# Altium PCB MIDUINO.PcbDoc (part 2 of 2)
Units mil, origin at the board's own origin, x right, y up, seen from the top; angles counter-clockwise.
Board outline 26720 x 2625 mil, 2 copper layers (Top Layer, Bottom Layer); 230 components, 129 nets, 640 pads, 170 vias.
Unrouted connection lines stored in the file: 1.
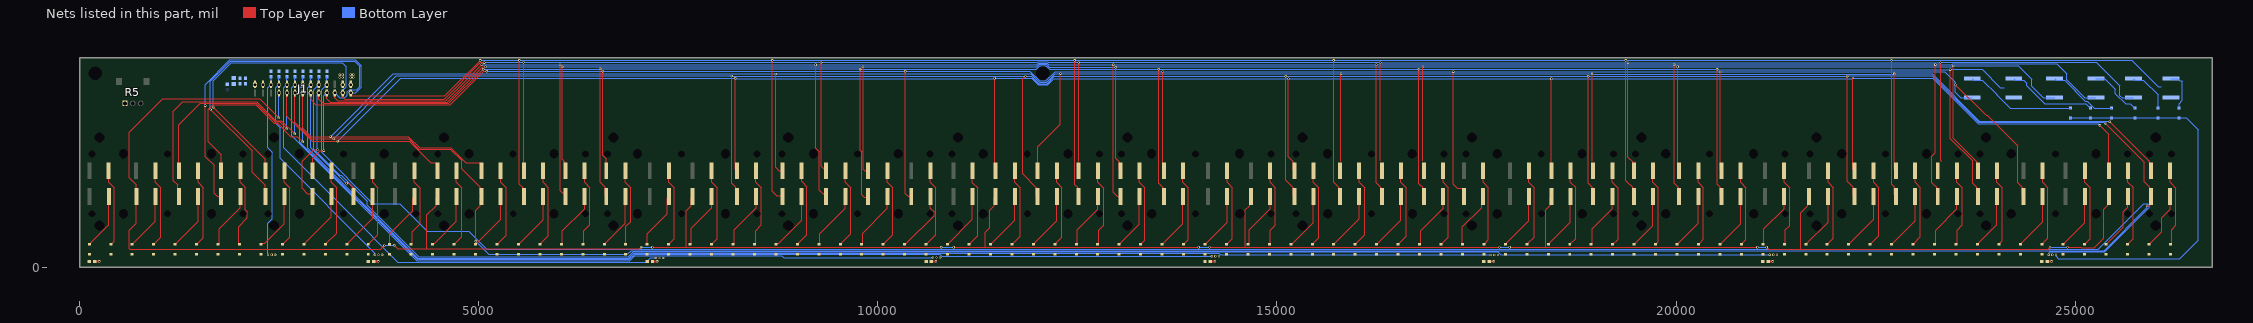
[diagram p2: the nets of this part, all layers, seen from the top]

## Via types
v1: diameter 30, hole 15, Top Layer to Bottom Layer, 145 vias
v2: diameter 54.72, hole 35.04, Top Layer to Bottom Layer, 25 vias

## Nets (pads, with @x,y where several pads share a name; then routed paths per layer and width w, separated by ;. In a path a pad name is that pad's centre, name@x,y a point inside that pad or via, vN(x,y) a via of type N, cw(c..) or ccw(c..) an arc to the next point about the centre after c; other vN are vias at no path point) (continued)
COL4: H4_ROW1.1 H4_ROW2.1 H4_ROW3.1 H4_ROW4.1 H4_ROW5.1 H4_ROW6.1 H4_ROW7.1 H4_ROW8.1 J1.8 | length 33504.2
  Top Layer w10: v1(2494.12,1869.12) 2494.12,1874.42 2258.54,2110 1042.63,2110 620,1687.37 620,1120.44 710,1030.44 H4_ROW1.1@710,885 710,546.93 625.14,462.07 625.14,229.86 631,224 3772.44,224 v1(3819,270.56) ; v1(3942.78,272.78) 3985.56,230 4350,230 ; H4_ROW2.1@4481,885 4466,870 4466,771 4350,655 4350,230 ; v1(7035,251) 7034.57,251 7013.57,230 4350,230 ; v1(7176.4,250.12) 7176.52,250 7600,250 ; H4_ROW3.1@7679,885 7665.86,871.86 7665.86,770.86 7600,705 7600,250 ; v1(10795,250.12) 10794.88,250 7600,250 ; v1(10950,250.12) 10950.12,250 11345,250 ; H4_ROW4.1@11476,886 11461.86,871.86 11461.86,771.86 11400.5,710.5 11400.5,490.5 11345,435 11345,250 ; v1(14019,250.12) 14018.88,250 11345,250 ; v1(14155,250.12) 14155.12,250 14606.35,250 ; H4_ROW5.1@14675,885 14660.86,870.86 14660.86,770.86 14606.35,716.35 14606.35,250 ; v1(17789,250.12) 17788.88,250 14606.35,250 ; v1(17915,250.12) 17915.12,250 18369.47,250 ; H4_ROW6.1@18438,885 18423,870 18423,773 18370.28,720.28 18370.28,250.81 18369.47,250 ; v1(21019,250.12) 21018.88,250 18369.47,250 ; v1(21135,250.12) 21135,250 21160,225 21556.25,225 ; H4_ROW7.1@21665,885 21650.86,870.86 21650.86,770.86 21561.25,681.25 21561.25,230 21556.25,225 ; v1(24685,250.12) 24685,247.43 24662.57,225 21561.25,225 21556.25,225 ; v1(24905,250.12) 25072.65,250.12 25077.76,245 25240,245 25358.92,363.92 25358.92,723.92 25407,772 25407,871 H4_ROW8.1@25422,886
  Bottom Layer w10: v1(2494.12,1869.12) 2496.06,1871.06 2496.06,2183.06 v2(2498,2185) ; v1(3819,270.56) 3820.11,271.67 3941.67,271.67 v1(3942.78,272.78) ; v1(7035,251) 7035.44,250.56 7175.96,250.56 v1(7176.4,250.12) ; v1(10795,250.12) v1(10950,250.12) ; v1(14019,250.12) v1(14155,250.12) ; v1(17789,250.12) v1(17915,250.12) ; v1(21019,250.12) v1(21135,250.12) ; v1(24685,250.12) v1(24905,250.12)
COL5: H5_ROW1.1 H5_ROW2.1 H5_ROW3.1 H5_ROW4.1 H5_ROW5.1 H5_ROW6.1 H5_ROW7.1 H5_ROW8.1 J1.10 | length 34308.3
  Top Layer w10: H5_ROW1.1@1244,1207 1244,1784 1514,2054 2213.37,2054 2448.69,1818.69 2507.77,1818.69 v1(2595.19,1731.27) ; v2(2598,2185) J1.10@2598,2180.08 2598,1892.51 2912.51,1578 4129.79,1578 4400.79,1307 4461,1307 4481,1287 H5_ROW2.1@4481,1207 ; v1(8214.64,2366) 8214.64,1226.36 H5_ROW3.1@8234,1207 ; v1(11462.97,2366) 11462.97,1221.03 H5_ROW4.1@11476,1208 ; v1(15145,2361) 15145,1380 15203.86,1321.14 15203.86,1221.14 H5_ROW5.1@15218,1207 ; H5_ROW6.1@18438,1207 18439.07,1208.07 v1(18439.07,2361) ; v1(22217,2369) 22216,2368 22216,1227 H5_ROW7.1@22236,1207 ; v1(25310,1775) 25422,1663 H5_ROW8.1@25422,1208
  Bottom Layer w10: v1(2595.19,1731.27) 2596.6,1732.67 2596.6,2183.6 v2(2598,2185) ; v1(3232.01,1578.48) 4022.54,2369 8157.04,2369 8158.04,2368 8179.58,2368 8180.58,2369 8211.64,2369 v1(8214.64,2366) ; v1@8214.64,2365.56 8217.2,2363 11459.96,2363 v1(11462.97,2366) ; v1@11463.97,2364 11927.35,2364 12007.35,2284 12126.75,2284 12203.58,2360.83 15144.83,2360.83 v1(15145,2361) ; v1@15145.08,2360.91 15145.17,2361 v1(18439.07,2361) ; v1@18439.07,2360.83 22203.42,2360.83 22211.59,2369 v1(22217,2369) ; v1@22220,2369 23216.25,2369 23788.25,1797 25288,1797 v1(25310,1775)
COL6: H6_ROW1.1 H6_ROW2.1 H6_ROW3.1 H6_ROW4.1 H6_ROW5.1 H6_ROW6.1 H6_ROW7.1 H6_ROW8.1 J1.12 | length 60224.7
  Top Layer w10: H6_ROW1.1@1245,885 1230.86,899.14 1230.86,1029.14 1175,1085 1175,1955 1290,2070 2220,2070 2455,1835 2528.23,1835 v1(2694.12,1669.12) ; v2(2698,2185) J1.12@2698,2180.08 2698,1815.14 2904.14,1609 v1(3184.23,1609) 4121.42,1609 4251.42,1479 4646,1479 4785,1340 4785,1235 5021,999 5021,900 H6_ROW2.1@5036,885 5021,870 5021,771 4963.22,713.22 v1(4963.22,324.72) ; v1(8168.81,2394) 8168.81,1445.53 8168.81,1051.19 8219,1001 8219,900 H6_ROW3.1@8234,885 ; v1(11850,2390) 11817.7,2357.7 11817.7,1167.3 11988,997 11988,900 H6_ROW4.1@12003,885 ; v1(15110,2390) 15110,1090 15203,997 15203,900 H6_ROW5.1@15218,885 ; v1(18901.66,2392.07) 18900.41,2390.82 18900.41,1049.59 18949.86,1000.14 18949.86,898.14 H6_ROW6.1@18962,886 ; v1(22146.03,2393) 22145,2391.97 22145,1075 22221,999 22221,900 H6_ROW7.1@22236,885 ; v1(25385,1795) 25865,1315 25865,1070 25935.86,999.14 25935.86,898.14 H6_ROW8.1@25949,885 ; v1(25900,770) 25940,770
  Bottom Layer w10: v1(2694.12,1669.12) 2696.06,1671.06 2696.06,2183.06 v2(2698,2185) ; v1(3184.23,1609) 3184.23,1614.23 3189.46,1614.23 3970.23,2395 8167.81,2395 8170.81,2392 11848,2392 v1(11850,2390) 11923.98,2390 12013.98,2300 12120.12,2300 12212.19,2392.07 15107.93,2392.07 v1(15110,2390) 15111.04,2391.04 18900.63,2391.04 18902.13,2392.54 22145.57,2392.54 v1(22146.03,2393) ; v1(4963.22,324.72) 4963.22,321.78 5125,160 6860,160 6908.12,208.12 25363.12,208.12 25900,745 v1(25900,770) ; v1@22148.72,2393.06 22150.66,2395 23212.88,2395 23794.88,1813 25361.59,1813 25379.59,1795 v1(25385,1795)
COL7: H7_ROW1.1 H7_ROW2.1 H7_ROW3.1 H7_ROW4.1 H7_ROW5.1 H7_ROW6.1 H7_ROW7.1 H7_ROW8.1 J1.14 | length 35615.5
  Top Layer w10: H7_ROW1.1@1774,1208 1774,1406 1610,1570 1610,1980 1666,2036 1839,2036 1840,2035 2205,2035 2440,1800 2480,1800 2645,1635 2728.23,1635 v1(2794.12,1569.12) ; v2(2798,2185) J1.14@2798,2180.08 2798,1737.76 2900.76,1635 v1(3145,1635) 4120,1635 4260,1495 4652.63,1495 4840.63,1307 5016,1307 5036,1287 H7_ROW2.1@5036,1207 ; v1(8720,2420) 8720,1250 8762,1208 H7_ROW3.1@8806,1208 ; H7_ROW4.1@12003,1207 12003,1505.85 12288.57,1791.43 v1(12288.57,2424) ; 15802.81,1327.81 v1(15802.81,2424) ; v1(18947,2421) 18950,2418 18950,1325 ; v1(22735.58,2421) 22736,2420.58 22736,1227 H7_ROW7.1@22756,1207 ; v1(25434,1821) 25929,1326 25929,1312 25949,1292 H7_ROW8.1@25949,1207
  Bottom Layer w10: v1(2794.12,1569.12) 2796.06,1571.06 2796.06,2183.06 v2(2798,2185) ; v1(3145,1635) 3931,2421 8719,2421 v1(8720,2420) 11916.61,2420 12020.61,2316 12113.49,2316 12221.49,2424 v1(15802.81,2424) 15805.81,2421 v1(18947,2421) ; v1@18947,2419 22733.58,2419 v1(22735.58,2421) ; v1@22736.16,2420.43 22737.31,2421.58 23208.93,2421.58 23800.51,1830 25419.59,1830 25428.59,1821 v1(25434,1821)
COL8: H13_ROW1.1 H13_ROW2.1 H13_ROW3.1 H13_ROW4.1 H13_ROW5.1 H13_ROW6.1 H13_ROW7.1 H13_ROW8.1 J1.16 | length 31775.4
  Top Layer w10: J1.16@2898,2180.08 v2(2898,2185) 2900,2183 2900,2095 2961,2034 4644,2034 5062.73,2452.73 v1(5100,2452.73) ; v1(3345,1050) 3370,1050 3420.86,999.14 3420.86,896.14 H13_ROW1.1@3432,885 ; v1(6553.74,2455.48) 6553.74,1401.47 6598,1357.21 H13_ROW2.1@6598,1207 ; v1(10345,2455) 10345,920 10380,885 H13_ROW3.1@10419,885 ; v1(13570,2451) 13570,1220 H13_ROW4.1@13583,1207 ; v1(17208,2450) 17208,1037 17260,985 17325,985 17345,965 H13_ROW5.1@17345,885 ; v1(20555,2445) 20555,1223 H13_ROW6.1@20570,1208 ; v1(23501,2284.57) 23885.2,1900.37 23899.63,1900.37 24280,1520 24280,1060 24339,1001 24339,900 H13_ROW7.1@24354,885
  Bottom Layer w10: v2(2898,2185) 2898,1492.6 3340.6,1050 v1(3345,1050) ; v1(5100,2452.73) 5101.38,2454.11 6552.37,2454.11 v1@6558.37,2460.11 ; v1(6553.74,2455.48) v1@6558.37,2460.11 ; v1@20552.53,2447.53 20555,2450 23367.63,2450 23501,2316.63 v1(23501,2284.57) ; v1(20555,2445) 20552.5,2447.5 17210.5,2447.5 17207.5,2450.5 13570.5,2450.5 v1(13570,2451) 13569,2450 12224.86,2450 12106.86,2332 12027.24,2332 11906.5,2452.73 10345,2452.73 10342.51,2455.23 6562.98,2455.23 6558.37,2459.84 v1@6558.37,2460.11 ; v1@23500,2281.92 23500,2190 23567.99,2122.01 H13_ROW8.1@23712,2122.01
COL9: H12_ROW1.1 H12_ROW2.1 H12_ROW3.1 H12_ROW4.1 H12_ROW5.1 H12_ROW6.1 H12_ROW7.1 H12_ROW8.1 J1.18 | length 32916.9
  Top Layer w10: H12_ROW1.1@2915,885 2915,900 2895,920 2855,920 2790,985 2790,1325 2935,1470 v1(2980,1470) ; v2(2998,2185) 2998,2102 3050,2050 4625,2050 5054.48,2479.49 v1(5056.25,2479.49) ; v1(6521.22,2484) 6521.22,1063.78 6583,1002 6583,900 H12_ROW2.1@6598,885 ; v1(9778.74,2481.23) 9778.74,1467.04 9800.3,1445.48 9800.3,904.7 9830,875 9870,875 H12_ROW3.1@9880,885 ; v1(13519,2479) 13520,2478 13520,1050 13570.86,999.14 13570.86,897.14 H12_ROW4.1@13583,885 ; v1(16779.25,2479.25) 16780,2478.5 16780,1045 16827,998 16827,900 H12_ROW5.1@16842,885 ; v1(20515,2476.53) 20515,1040 20555,1000 20555,901 H12_ROW6.1@20570,886 ; v1(23435,2475) 23435,1610 23715,1330 23715,1050 23766,999 23766,900 H12_ROW7.1@23781,885
  Bottom Layer w10: v1(2980,1470) 2980,2154.9 2998,2172.9 v2(2998,2185) ; v1(5056.25,2479.49) 5058.51,2481.74 6518.96,2481.74 v1(6521.22,2484) ; v1@6523.22,2482.61 9777.36,2482.61 v1(9778.74,2481.23) 11983.85,2481.23 12026.63,2524 12106.76,2524 12154.69,2476.07 13516.07,2476.07 13519.5,2479.5 13519.88,2479.12 16779.12,2479.12 v1(16779.25,2479.25) 16782.43,2476.07 v1@20514.93,2476.07 ; v1(20515,2476.53) 20515.76,2475.76 23434.69,2475.76 23435,2476.07 23838.93,2476.07 24065,2250 24110,2250
COL10: H11_ROW1.1 H11_ROW2.1 H11_ROW3.1 H11_ROW4.1 H11_ROW5.1 H11_ROW6.1 H11_ROW7.1 H11_ROW8.1 J1.20 | length 31087.7
  Top Layer w10: H11_ROW1.1@2915,1207 2920,1212 2920,1365 3015,1460 v1(3060,1460) ; v2(3098,2185) J1.20@3098,2180.08 3098,2107 3139,2066 4606,2066 5050,2510 v1(5085,2510) ; v1(6045,2510) 6045,1349 6072.86,1321.14 6072.86,1307 6074.73,1305.13 H11_ROW2.1@6088.87,1305.13 ; v1(9815,2510) 9816.3,2508.7 9816.3,1228.7 9835,1210 9878,1210 H11_ROW3.1@9880,1208 ; v1(12980,2505) 12980,1365 13023,1322 13023,1223 H11_ROW4.1@13038,1208 ; 16830,1330 v1(16830,2510) ; v1(20020,2510.12) 20020,1227 H11_ROW6.1@20040,1207 ; v1(23475,2520) 23475,1615 23768.86,1321.14 23768.86,1219.14 H11_ROW7.1@23781,1207
  Bottom Layer w10: v1(3060,1460) 3060,2147 v2(3098,2185) ; v1(5085,2510) v1(6045,2510) v1(9815,2510) 11990,2510 12020,2540 12113.39,2540 12148.39,2505 12974.88,2505 12980,2510.12 v1(20020,2510.12) ; v1@20022.42,2510.12 23459.7,2510.12 23469.59,2520 24290,2520 24455,2355 24455,2267.19 24600.18,2122.01 H11_ROW8.1@24742,2122.01
COL11: H10_ROW1.1 H10_ROW2.1 H10_ROW3.1 H10_ROW4.1 H10_ROW5.1 H10_ROW6.1 H10_ROW7.1 H10_ROW8.1 J1.22 | length 37148.9
  Top Layer w10: v1(1640.88,1974.12) 2160,1455 2160,1190 2327,1023 H10_ROW1.1@2327,885 ; v2(3198,2185) 3198,2122 3235,2085 4585,2085 5038,2538 v1(5039,2538) ; v1(6018.88,2536.12) 6018.88,956.12 6044.74,930.26 6067,930.26 6087,910.26 H10_ROW2.1@6087,885 ; v1(9221.12,2536.12) 9221.12,1490.47 9265,1446.58 9265,965 9319.86,910.14 9334,910.14 9354,890.14 H10_ROW3.1@9354,885 ; v1(12948.88,2536.12) 12948.88,936.12 12999,886 H10_ROW4.1@13038,886 ; v1(16245,2538) 16245,1055 16299.86,1000.14 16299.86,900.14 H10_ROW5.1@16314,886 ; v1(19976.12,2536.12) 19976.12,1048.88 20025.86,999.14 20025.86,899.14 H10_ROW6.1@20040,885 ; v1(23250,2537) 23250,1434.42 23205,1389.42 23205,1060 23265.86,999.14 23265.86,898.14 H10_ROW7.1@23279,885
  Bottom Layer w10: v1(1640.88,1974.12) 1640,1975 1640,2330 1889,2579 3445.14,2579 3510,2514.14 3510,2260 3473.36,2223.36 3382.11,2223.36 3355,2196.25 3355,2155 3324.96,2124.96 3258.04,2124.96 v2(3198,2185) ; v1(5039,2538) 5040.88,2536.12 v1(6018.88,2536.12) v1(9221.12,2536.12) 11991.12,2536.12 12011,2556 12120.02,2556 12139.9,2536.12 v1(12948.88,2536.12) 12949.83,2537.06 16244.06,2537.06 v1(16245,2538) ; v1@16245,2540 16248.88,2536.12 v1(19976.12,2536.12) 19976.56,2536.56 23249.56,2536.56 v1(23250,2537) ; v1@23251.5,2538.5 23253.88,2536.12 23454.35,2536.12 23464.23,2546 24769,2546 24895,2420 24895,2345 25117.99,2122.01 H10_ROW8.1@25261,2122.01
COL12: H9_ROW1.1 H9_ROW2.1 H9_ROW3.1 H9_ROW4.1 H9_ROW5.1 H9_ROW6.1 H9_ROW7.1 H9_ROW8.1 J1.24 | length 34255
  Top Layer w10: v1(1675,2005) 2327,1353 H9_ROW1.1@2327,1207 ; v2(3298,2185) 3299.14,2183.86 3299.14,2125.86 3320,2105 4568.23,2105 5027.23,2564 5068.68,2564 v1(5070.57,2562.12) ; v1(5561.34,2566) 5561.34,1292.66 H9_ROW2.1@5565,1289 ; v1(9290,2564) 9290,1265 9319.86,1235.14 9334,1235.14 9354,1215.14 H9_ROW3.1@9354,1208 ; 12515,1325 12515,2563.81 v1(12515.19,2564) ; v1(16294.5,2564) 16295,2563.5 16295,1330 ; v1(19398,2562.12) 19398,1377 19456,1319 19456,1222 H9_ROW6.1@19471,1207 ; 19480,1320 19482.86,1317.14 19491.14,1317.14 ; v1(23313.41,2564) 23314,2563.41 23314,1331 23320,1325
  Bottom Layer w10: v1(1675,2005) 1675,2335 1900,2560 3288,2560 3340,2508 3340,2260 3301.45,2221.45 3301.45,2188.45 v2(3298,2185) ; v1(5070.57,2562.12) 5072.45,2564 5559.34,2564 v1(5561.34,2566) 5563.34,2564 v1(9290,2564) 10710.15,2564 11994,2564 12002,2572 12126.65,2572 12134.65,2564 v1(12515.19,2564) ; v1@12515.51,2564.33 12515.84,2564 v1(16294.5,2564) 16295.5,2563 19397.12,2563 v1(19398,2562.12) ; v1@19398.06,2562.06 19399,2563 23312.41,2563 v1(23313.41,2564) 25266,2564 25560,2270 25560,2150 25587.99,2122.01 H9_ROW8.1@25731,2122.01
COL13: H8_ROW1.1 H8_ROW2.1 H8_ROW3.1 H8_ROW4.1 H8_ROW5.1 H8_ROW6.1 H8_ROW7.1 H8_ROW8.1 J1.26 | length 37547
  Top Layer w10: v1(1575,2023) 1575,1385 1685,1275 1685,925 1724,886 H8_ROW1.1@1774,886 ; v2(3398,2185) 3398,2154.96 3407.96,2145 4577.49,2145 5020,2587.51 v1(5020,2590) ; v1(5510,2590) 5510,1040 5552,998 5552,900 H8_ROW2.1@5567,885 ; v1(8680,2590) 8680,950 8735,895 8796,895 H8_ROW3.1@8806,885 ; v1(12465,2590) 12465,1035 12502,998 12502,901 H8_ROW4.1@12517,886 ; v1(15710,2590) 15710,1065 15776,999 15776,901 H8_ROW5.1@15791,886 ; v1(19371.01,2590) 19371.01,1083.99 19456,999 19456,900 H8_ROW6.1@19471,885 ; v1(22700,2590) 22700,1040 22736,1004 22736,905 H8_ROW7.1@22756,885
  Bottom Layer w10: v1(1575,2023) 1575,2287.63 1882.37,2595 3451.77,2595 3526,2520.77 3526,2251 3460,2185 v2(3398,2185) ; v1(5020,2590) v1(5510,2590) 5512,2592 8678,2592 v1(8680,2590) v1(12465,2590) v1(15710,2590) v1(19371.01,2590) v1(22700,2590) 25710,2590 26040,2260 26080,2260
GND: C1.1 C2.2 C3.1 C4_ROW1.1 C4_ROW2.1 C4_ROW3.1 C4_ROW4.1 C4_ROW5.1 C4_ROW6.1 C4_ROW7.1 C4_ROW8.1 J1.23 J1.25 R5.1 R6_ROW1.1 R6_ROW2.1 R6_ROW3.1 R6_ROW4.1 R6_ROW5.1 R6_ROW6.1 R6_ROW7.1 R6_ROW8.1 | length 465.5
  Top Layer w25: R6_ROW1.1@188.46,72 v1@246.65,72 ; R6_ROW2.1@3683.46,72 v1(3741.65,72) ; R6_ROW3.1@7177.1,72 v1(7235.29,72) ; R6_ROW4.1@10671.42,72 v1(10729.61,72) ; R6_ROW5.1@14165.74,72 v1(14223.93,72) ; R6_ROW6.1@17660.06,72 v1(17718.25,72) ; R6_ROW7.1@21154.38,72 v1(21212.57,72) ; R6_ROW8.1@24648.7,72 v1(24706.89,72)
  other v1: 246.65,72 3260,2375 3295,2375 3395,2375 3430,2375 3260,2410 3295,2410 3395,2410 3430,2410
  other v2: 3298,2285 3398,2285
NetD1_ROW1_1: D1_ROW1.1 H1_ROW1.2 | length 966.4
  Top Layer w10: H1_ROW1.2@365,1207 365,1061.55 432,994.55 432,326.23 391.78,286.01 D1_ROW1.1@390.79,286.01
NetD1_ROW2_1: D1_ROW2.1 H1_ROW2.2 | length 999.3
  Top Layer w10: D1_ROW2.1@3616.32,286.01 3617.3,286.01 3630.02,298.72 3630.02,299.71 3738,407.69 3738,994.55 3672,1060.55 H1_ROW2.2@3672,1207
NetD1_ROW3_1: D1_ROW3.1 H1_ROW3.2 | length 979.4
  Top Layer w10: D1_ROW3.1@7379.43,286.01 7380.42,286.01 7393.13,298.72 7393.13,299.71 7451,357.58 7451,992.55 7383,1060.55 H1_ROW3.2@7383,1207
NetD1_ROW4_1: D1_ROW4.1 H1_ROW4.2 | length 1000.3
  Top Layer w10: D1_ROW4.1@10604.96,286.01 10605.94,286.01 10618.66,298.72 10618.66,299.71 10727,408.05 10727,992.55 10659,1060.55 H1_ROW4.2@10659,1207
NetD1_ROW5_1: D1_ROW5.1 H1_ROW5.2 | length 978.3
  Top Layer w10: D1_ROW5.1@14368.07,286.01 14369.06,286.01 14381.77,298.72 14381.77,299.71 14440,357.94 14440,995.55 14375,1060.55 H1_ROW5.2@14375,1207
NetD1_ROW6_1: D1_ROW6.1 H1_ROW6.2 | length 971.9
  Top Layer w10: H1_ROW6.2@17585,1207 17585,1060.55 17650,995.55 17650,342.41 17607.3,299.71 17607.3,298.72 17594.58,286.01 D1_ROW6.1@17593.6,286.01
NetD1_ROW7_1: D1_ROW7.1 H1_ROW7.2 | length 976.6
  Top Layer w10: H1_ROW7.2@21355,1207 21355,1060.55 21422.3,993.25 21422.3,521.05 21370.41,469.16 21370.41,298.72 21357.69,286.01 D1_ROW7.1@21356.71,286.01
NetD1_ROW8_1: D1_ROW8.1 H1_ROW8.2 | length 981.1
  Top Layer w10: D1_ROW8.1@24582.24,286.01 24583.22,286.01 24595.94,298.72 24595.94,299.71 24660,363.77 24660,994.55 24594,1060.55 H1_ROW8.2@24594,1207
NetD2_ROW1_1: D2_ROW1.1 H2_ROW1.2 | length 700.6
  Top Layer w10: D2_ROW1.1@122,286.01 122.98,286.01 366,529.02 H2_ROW1.2@366,885
NetD2_ROW2_1: D2_ROW2.1 H2_ROW2.2 | length 726.9
  Top Layer w10: D2_ROW2.1@3885.11,286.01 3885.11,417.9 4174,706.79 4174,865 H2_ROW2.2@4194,885
NetD2_ROW3_1: D2_ROW3.1 H2_ROW3.2 | length 711.8
  Top Layer w10: D2_ROW3.1@7110.64,286.01 7110.64,415.68 7363,668.04 7363,865 H2_ROW3.2@7383,885
NetD2_ROW4_1: D2_ROW4.1 H2_ROW4.2 | length 727.9
  Top Layer w10: D2_ROW4.1@10873.75,286.01 10874.74,286.01 11186,597.27 H2_ROW4.2@11186,884
NetD2_ROW5_1: D2_ROW5.1 H2_ROW5.2 | length 713.8
  Top Layer w10: D2_ROW5.1@14099.28,286.01 14100.26,286.01 14375,560.75 H2_ROW5.2@14375,885
NetD2_ROW6_1: D2_ROW6.1 H2_ROW6.2 | length 722
  Top Layer w10: D2_ROW6.1@17862.39,286.01 17863.38,286.01 18158,580.63 H2_ROW6.2@18158,885
NetD2_ROW7_1: D2_ROW7.1 H2_ROW7.2 | length 710.2
  Top Layer w10: D2_ROW7.1@21087.92,286.01 21088.9,286.01 21101.62,298.72 21101.62,479.41 21355,732.79 H2_ROW7.2@21355,885
NetD2_ROW8_1: D2_ROW8.1 H2_ROW8.2 | length 712.4
  Top Layer w10: D2_ROW8.1@24851.03,286.01 24852.01,286.01 25121,554.99 H2_ROW8.2@25121,886
NetD3_ROW1_1: D3_ROW1.1 H3_ROW1.2 | length 984.8
  Top Layer w10: D3_ROW1.1@928.38,286.01 929.37,286.01 1015,371.64 1015,995.55 949,1061.55 H3_ROW1.2@949,1207
NetD3_ROW2_1: D3_ROW2.1 H3_ROW2.2 | length 998.9
  Top Layer w10: D3_ROW2.1@4153.91,286.01 4154.89,286.01 4167.61,298.72 4167.61,445.26 4267.3,544.95 4267.3,987.25 4194,1060.55 H3_ROW2.2@4194,1207
NetD3_ROW3_1: D3_ROW3.1 H3_ROW3.2 | length 978.7
  Top Layer w10: D3_ROW3.1@7917.02,286.01 7918,286.01 7930.72,298.72 7930.72,299.71 7987,355.99 7987,992.55 7919,1060.55 H3_ROW3.2@7919,1207
NetD3_ROW4_1: D3_ROW4.1 H3_ROW4.2 | length 992.4
  Top Layer w10: D3_ROW4.1@11142.55,286.01 11143.53,286.01 11156.25,298.72 11156.25,299.71 11251,394.46 11251,994.55 11186,1059.55 H3_ROW4.2@11186,1206
NetD3_ROW5_1: D3_ROW5.1 H3_ROW5.2 | length 981.2
  Top Layer w10: D3_ROW5.1@14905.66,286.01 14906.64,286.01 14919.36,298.72 14919.36,463.64 14982.3,526.58 14982.3,993.25 14915,1060.55 H3_ROW5.2@14915,1207
NetD3_ROW6_1: D3_ROW6.1 H3_ROW6.2 | length 985.7
  Top Layer w10: D3_ROW6.1@18131.18,286.01 18132.17,286.01 18144.89,298.72 18144.89,299.71 18222,376.82 18222,996.55 18158,1060.55 H3_ROW6.2@18158,1207
NetD3_ROW7_1: D3_ROW7.1 H3_ROW7.2 | length 979.8
  Top Layer w10: D3_ROW7.1@21894.3,286.01 21895.28,286.01 21908,298.72 21908,299.71 21970,361.71 21970,995.55 21905,1060.55 H3_ROW7.2@21905,1207
NetD3_ROW8_1: D3_ROW8.1 H3_ROW8.2 | length 977.7
  Top Layer w10: D3_ROW8.1@25119.82,286.01 25120.81,286.01 25133.52,298.72 25133.52,299.71 25187,353.18 25187,995.55 25121,1061.55 H3_ROW8.2@25121,1208
NetD4_ROW1_1: D4_ROW1.1 H4_ROW1.2 | length 719.9
  Top Layer w10: D4_ROW1.1@659.59,286.01 660.57,286.01 950,575.44 H4_ROW1.2@950,885
NetD4_ROW2_1: D4_ROW2.1 H4_ROW2.2 | length 729
  Top Layer w10: D4_ROW2.1@4422.7,286.01 4435.42,298.72 4446.38,298.72 4721,573.35 H4_ROW2.2@4721,885
NetD4_ROW3_1: D4_ROW3.1 H4_ROW3.2 | length 711.7
  Top Layer w10: D4_ROW3.1@7648.23,286.01 7649.21,286.01 7661.93,298.72 7661.93,486.93 7919,744 H4_ROW3.2@7919,885
NetD4_ROW4_1: D4_ROW4.1 H4_ROW4.2 | length 726.8
  Top Layer w10: D4_ROW4.1@11411.34,286.01 11412.32,286.01 11716,589.68 H4_ROW4.2@11716,886
NetD4_ROW5_1: D4_ROW5.1 H4_ROW5.2 | length 714.8
  Top Layer w10: D4_ROW5.1@14636.87,286.01 14637.85,286.01 14650.57,298.72 14650.57,468.36 14915,732.79 H4_ROW5.2@14915,885
NetD4_ROW6_1: D4_ROW6.1 H4_ROW6.2 | length 714.7
  Top Layer w10: D4_ROW6.1@18399.98,286.01 18400.96,286.01 18678,563.05 H4_ROW6.2@18678,885
NetD4_ROW7_1: D4_ROW7.1 H4_ROW7.2 | length 716
  Top Layer w10: D4_ROW7.1@21625.5,286.01 21638.22,298.72 21640.38,298.72 21905,563.35 H4_ROW7.2@21905,885
NetD4_ROW8_1: D4_ROW8.1 H4_ROW8.2 | length 713.8
  Top Layer w10: D4_ROW8.1@25388.62,286.01 25389.6,286.01 25604.7,501.11 25604.7,691.49 25662,748.79 H4_ROW8.2@25662,886
NetD5_ROW1_1: D5_ROW1.1 H5_ROW1.2 | length 984.5
  Top Layer w10: D5_ROW1.1@1465.97,286.01 1466.95,286.01 1551,370.05 1551,994.55 1484,1061.55 H5_ROW1.2@1484,1207
NetD5_ROW2_1: D5_ROW2.1 H5_ROW2.2 | length 988.5
  Top Layer w10: D5_ROW2.1@4691.49,286.01 4692.48,286.01 4705.2,298.72 4705.2,299.71 4787,381.51 4787,994.55 4721,1060.55 H5_ROW2.2@4721,1207
NetD5_ROW3_1: D5_ROW3.1 H5_ROW3.2 | length 987.2
  Top Layer w10: D5_ROW3.1@8454.61,286.01 8455.59,286.01 8468.31,298.72 8468.31,458.11 8542.3,532.1 8542.3,992.25 8474,1060.55 H5_ROW3.2@8474,1208
NetD5_ROW4_1: D5_ROW4.1 H5_ROW4.2 | length 992.9
  Top Layer w10: D5_ROW4.1@11680.13,286.01 11681.12,286.01 11693.83,298.72 11693.83,299.71 11783,388.87 11783,994.55 11716,1061.55 H5_ROW4.2@11716,1208
NetD5_ROW5_1: D5_ROW5.1 H5_ROW5.2 | length 981.5
  Top Layer w10: D5_ROW5.1@15443.25,286.01 15444.23,286.01 15456.95,298.72 15456.95,299.71 15523,365.76 15523,995.55 15458,1060.55 H5_ROW5.2@15458,1207
NetD5_ROW6_1: D5_ROW6.1 H5_ROW6.2 | length 977.6
  Top Layer w10: D5_ROW6.1@18668.77,286.01 18669.76,286.01 18682.47,298.72 18682.47,299.71 18741,358.24 18741,997.55 18678,1060.55 H5_ROW6.2@18678,1207
NetD5_ROW7_1: D5_ROW7.1 H5_ROW7.2 | length 993.7
  Top Layer w10: D5_ROW7.1@22431.89,286.01 22432.87,286.01 22445.59,298.72 22445.59,299.71 22541,395.12 22541,995.55 22476,1060.55 H5_ROW7.2@22476,1207
NetD5_ROW8_1: D5_ROW8.1 H5_ROW8.2 | length 977.5
  Top Layer w10: D5_ROW8.1@25657.41,286.01 25658.4,286.01 25726,353.61 25726,997.55 25662,1061.55 H5_ROW8.2@25662,1208
NetD6_ROW1_1: D6_ROW1.1 H6_ROW1.2 | length 718.8
  Top Layer w10: D6_ROW1.1@1197.18,286.01 1198.16,286.01 1485,572.85 H6_ROW1.2@1485,885
NetD6_ROW2_1: D6_ROW2.1 H6_ROW2.2 | length 730.3
  Top Layer w10: D6_ROW2.1@4960.29,286.01 4961.27,286.01 5276,600.74 H6_ROW2.2@5276,885
NetD6_ROW3_1: D6_ROW3.1 H6_ROW3.2 | length 719.3
  Top Layer w10: D6_ROW3.1@8185.81,286.01 8186.8,286.01 8199.51,298.72 8199.51,469.51 8474.48,744.48 8474.48,884.52 H6_ROW3.2@8474,885
NetD6_ROW4_1: D6_ROW4.1 H6_ROW4.2 | length 721.4
  Top Layer w10: D6_ROW4.1@11948.93,286.01 11949.91,286.01 12243,579.1 H6_ROW4.2@12243,885
NetD6_ROW5_1: D6_ROW5.1 H6_ROW5.2 | length 724.2
  Top Layer w10: D6_ROW5.1@15174.45,286.01 15187.17,298.72 15200.38,298.72 15458,556.35 H6_ROW5.2@15458,885
NetD6_ROW6_1: D6_ROW6.1 H6_ROW6.2 | length 710.1
  Top Layer w10: D6_ROW6.1@18937.57,286.01 18938.55,286.01 18951.27,298.72 18951.27,478.06 19202,728.79 H6_ROW6.2@19202,886
NetD6_ROW7_1: D6_ROW7.1 H6_ROW7.2 | length 729.2
  Top Layer w10: D6_ROW7.1@22163.09,286.01 22164.08,286.01 22476,597.93 H6_ROW7.2@22476,885
NetD6_ROW8_1: D6_ROW8.1 H6_ROW8.2 | length 708.4
  Top Layer w10: D6_ROW8.1@25926.2,286.01 25927.19,286.01 26084,442.82 26084,620.79 26189,725.79 H6_ROW8.2@26189,885
NetD7_ROW1_1: D7_ROW1.1 H7_ROW1.2 | length 1007.6
  Top Layer w10: D7_ROW1.1@2003.56,286.01 1993.7,295.86 1993.7,508.4 2102.3,617 2102.3,692 2078,716.3 2078,997.55 2014,1061.55 H7_ROW1.2@2014,1208
NetD7_ROW2_1: D7_ROW2.1 H7_ROW2.2 | length 996.5
  Top Layer w10: D7_ROW2.1@5229.08,286.01 5230.07,286.01 5242.78,298.72 5242.78,299.71 5343,399.93 5343,993.55 5276,1060.55 H7_ROW2.2@5276,1207
NetD7_ROW3_1: D7_ROW3.1 H7_ROW3.2 | length 997.5
  Top Layer w10: D7_ROW3.1@8992.2,286.01 8993.18,286.01 9005.9,298.72 9005.9,299.71 9112,405.81 9112,1008 9046,1074 H7_ROW3.2@9046,1206
NetD7_ROW4_1: D7_ROW4.1 H7_ROW4.2 | length 985.1
  Top Layer w10: D7_ROW4.1@12217.72,286.01 12218.71,286.01 12231.42,298.72 12231.42,299.71 12307,375.29 12307,996.55 12243,1060.55 H7_ROW4.2@12243,1207
NetD7_ROW5_1: D7_ROW5.1 H7_ROW5.2 | length 998.9
  Top Layer w10: D7_ROW5.1@15980.83,286.01 15981.82,286.01 15994.53,298.72 15994.53,299.71 16098,403.17 16098,994.55 16031,1061.55 H7_ROW5.2@16031,1208
NetD7_ROW6_1: D7_ROW6.1 H7_ROW6.2 | length 979.8
  Top Layer w10: H7_ROW6.2@19202,1208 19202,1061.55 19273.3,990.25 19273.3,351.96 19207.34,286.01 D7_ROW6.1@19206.36,286.01
NetD7_ROW7_1: D7_ROW7.1 H7_ROW7.2 | length 987.2
  Top Layer w10: D7_ROW7.1@22969.47,286.01 22970.46,286.01 22983.17,298.72 22983.17,299.71 23062,378.53 23062,994.55 22996,1060.55 H7_ROW7.2@22996,1207
NetD7_ROW8_1: D7_ROW8.1 H7_ROW8.2 | length 980.6
  Top Layer w10: H7_ROW8.2@26189,1207 26189,1060.55 26263.3,986.25 26263.3,522.41 26208.7,467.81 26208.7,298.72 26195.98,286.01 D7_ROW8.1@26195,286.01
NetD8_ROW1_1: D8_ROW1.1 H8_ROW1.2 | length 716.2
  Top Layer w10: D8_ROW1.1@1734.76,286.01 1735.75,286.01 1748.46,298.72 1748.46,478.46 2014,744 H8_ROW1.2@2014,886
NetD8_ROW2_1: D8_ROW2.1 H8_ROW2.2 | length 727.6
  Top Layer w10: D8_ROW2.1@5497.88,286.01 5498.86,286.01 5807,594.15 H8_ROW2.2@5807,885
NetD8_ROW3_1: D8_ROW3.1 H8_ROW3.2 | length 745.8
  Top Layer w10: D8_ROW3.1@8723.4,286.01 8736.12,298.72 8760.38,298.72 9046,584.35 H8_ROW3.2@9046,884
NetD8_ROW4_1: D8_ROW4.1 H8_ROW4.2 | length 712.6
  Top Layer w10: D8_ROW4.1@12486.51,286.01 12487.5,286.01 12500.22,298.72 12500.22,467.01 12757,723.79 H8_ROW4.2@12757,886
NetD8_ROW5_1: D8_ROW5.1 H8_ROW5.2 | length 732.7
  Top Layer w10: D8_ROW5.1@15712.04,286.01 15713.02,286.01 16031,603.98 H8_ROW5.2@16031,886
NetD8_ROW6_1: D8_ROW6.1 H8_ROW6.2 | length 697.3
  Top Layer w10: D8_ROW6.1@19475.15,286.01 19476.14,286.01 19711,520.87 H8_ROW6.2@19711,885
NetD8_ROW7_1: D8_ROW7.1 H8_ROW7.2 | length 721.9
  Top Layer w10: D8_ROW7.1@22700.68,286.01 22701.66,286.01 22996,580.34 H8_ROW7.2@22996,885
NetD8_ROW8_1: D8_ROW8.1 H8_ROW8.2 | length 506.6
  Bottom Layer w10: H8_ROW8.2@26201,2362.01 26281,2362.01 26310,2333.01 26335.56,2333.01 26342,2326.56 26342,2087.45 26301.69,2047.14 D8_ROW8.1@26301.69,1992.32
NetD9_ROW1_1: D9_ROW1.1 H9_ROW1.2 | length 985.3
  Top Layer w10: D9_ROW1.1@2541.14,286.01 2542.13,286.01 2631,374.88 2631,996.55 2567,1060.55 H9_ROW1.2@2567,1207
NetD9_ROW2_1: D9_ROW2.1 H9_ROW2.2 | length 993
  Top Layer w10: D9_ROW2.1@5766.67,286.01 5767.65,286.01 5780.37,298.72 5780.37,299.71 5873,392.34 5873,994.55 5807,1060.55 H9_ROW2.2@5807,1207
NetD9_ROW3_1: D9_ROW3.1 H9_ROW3.2 | length 1004.7
  Top Layer w10: D9_ROW3.1@9529.78,286.01 9530.77,286.01 9543.48,298.72 9543.48,299.71 9661,417.22 9661,994.55 9594,1061.55 H9_ROW3.2@9594,1208
NetD9_ROW4_1: D9_ROW4.1 H9_ROW4.2 | length 986.5
  Top Layer w10: D9_ROW4.1@12755.31,286.01 12756.29,286.01 12769.01,298.72 12769.01,462.96 12833.3,527.25 12833.3,985.25 12757,1061.55 H9_ROW4.2@12757,1208
NetD9_ROW5_1: D9_ROW5.1 H9_ROW5.2 | length 991.2
  Top Layer w10: D9_ROW5.1@16518.42,286.01 16519.41,286.01 16532.12,298.72 16532.12,299.71 16619,386.59 16619,996.55 16554,1061.55 H9_ROW5.2@16554,1208
NetD9_ROW6_1: D9_ROW6.1 H9_ROW6.2 | length 960.9
  Top Layer w10: H9_ROW6.2@19711,1207 19711,1060.55 19775,996.55 19775,317.06 19757.65,299.71 19757.65,298.72 19744.93,286.01 D9_ROW6.1@19743.95,286.01
NetD9_ROW7_1: D9_ROW7.1 H9_ROW7.2 | length 983.1
  Top Layer w10: D9_ROW7.1@23507.06,286.01 23508.04,286.01 23520.76,298.72 23520.76,461.84 23587.3,528.38 23587.3,992.25 23519,1060.55 H9_ROW7.2@23519,1207
NetD9_ROW8_1: D9_ROW8.1 H9_ROW8.2 | length 559.1
  Bottom Layer w10: H9_ROW8.2@25731,2362.01 25751,2342.01 25856.56,2342.01 26039,2159.56 D9_ROW8.1@26039,1992.32
NetD10_ROW1_1: D10_ROW1.1 H10_ROW1.2 | length 741.7
  Top Layer w10: D10_ROW1.1@2272.35,286.01 2285.07,298.72 2320.38,298.72 2567,545.35 H10_ROW1.2@2567,885
NetD10_ROW2_1: D10_ROW2.1 H10_ROW2.2 | length 720.3
  Top Layer w10: D10_ROW2.1@6035.46,286.01 6036.45,286.01 6049.16,298.72 6049.16,455.96 6327,733.79 H10_ROW2.2@6327,885
NetD10_ROW3_1: D10_ROW3.1 H10_ROW3.2 | length 738.5
  Top Layer w10: D10_ROW3.1@9260.99,286.01 9261.97,286.01 9274.69,298.72 9274.69,419.69 9594,739 H10_ROW3.2@9594,886
NetD10_ROW4_1: D10_ROW4.1 H10_ROW4.2 | length 705.7
  Top Layer w10: D10_ROW4.1@13024.1,286.01 13025.09,286.01 13278,538.92 H10_ROW4.2@13278,886
NetD10_ROW5_1: D10_ROW5.1 H10_ROW5.2 | length 726.6
  Top Layer w10: D10_ROW5.1@16249.63,286.01 16250.61,286.01 16554,589.4 H10_ROW5.2@16554,886
NetD10_ROW6_1: D10_ROW6.1 H10_ROW6.2 | length 710.3
  Top Layer w10: D10_ROW6.1@20012.74,286.01 20013.73,286.01 20280,552.28 H10_ROW6.2@20280,885
NetD10_ROW7_1: D10_ROW7.1 H10_ROW7.2 | length 715.9
  Top Layer w10: D10_ROW7.1@23238.27,286.01 23239.25,286.01 23251.97,298.72 23251.97,464.76 23519,731.79 H10_ROW7.2@23519,885
NetD10_ROW8_1: D10_ROW8.1 H10_ROW8.2 | length 670.9
  Bottom Layer w10: H10_ROW8.2@25261,2362.01 25266,2357.01 25372.99,2357.01 25504.76,2225.24 25504.76,2172.69 25631.21,2046.25 25693.09,2046.25 25747.02,1992.32 D10_ROW8.1@25748,1992.32
NetD11_ROW1_1: D11_ROW1.1 H11_ROW1.2 | length 1006.2
  Top Layer w10: D11_ROW1.1@3078.73,286.01 3079.72,286.01 3092.43,298.72 3092.43,299.71 3219,426.28 3219,996.55 3155,1060.55 H11_ROW1.2@3155,1207
NetD11_ROW2_1: D11_ROW2.1 H11_ROW2.2 | length 985.9
  Top Layer w10: D11_ROW2.1@6304.26,286.01 6305.24,286.01 6317.96,298.72 6317.96,457.44 6393.3,532.78 6393.3,745.7 6393,746 6393,994.55 6327,1060.55 H11_ROW2.2@6327,1207
NetD11_ROW3_1: D11_ROW3.1 H11_ROW3.2 | length 998.2
  Top Layer w10: D11_ROW3.1@10067.37,286.01 10068.35,286.01 10081.07,298.72 10081.07,299.71 10185,403.64 10185,996.55 10120,1061.55 H11_ROW3.2@10120,1208
NetD11_ROW4_1: D11_ROW4.1 H11_ROW4.2 | length 971.1
  Top Layer w10: H11_ROW4.2@13278,1208 13278,1061.55 13344,995.55 13344,337.11 13306.6,299.71 13306.6,298.72 13293.88,286.01 D11_ROW4.1@13292.9,286.01
NetD11_ROW5_1: D11_ROW5.1 H11_ROW5.2 | length 986.4
  Top Layer w10: D11_ROW5.1@17056.01,286.01 17056.99,286.01 17147.3,376.31 17147.3,995.25 17082,1060.55 H11_ROW5.2@17082,1207
NetD11_ROW6_1: D11_ROW6.1 H11_ROW6.2 | length 974
  Top Layer w10: H11_ROW6.2@20280,1207 20280,1060.55 20344,996.55 20344,348.47 20295.24,299.71 20295.24,298.72 20282.52,286.01 D11_ROW6.1@20281.53,286.01
NetD11_ROW7_1: D11_ROW7.1 H11_ROW7.2 | length 965.6
  Top Layer w10: H11_ROW7.2@24021,1207 24021,1060.55 24086,995.55 24086,327.36 24058.35,299.71 24058.35,298.72 24045.63,286.01 D11_ROW7.1@24044.65,286.01
NetD11_ROW8_1: D11_ROW8.1 H11_ROW8.2 | length 868.4
  Bottom Layer w10: H11_ROW8.2@24742,2362.01 24762,2342.01 24867.56,2342.01 25001.5,2208.06 25001.5,2205.95 25126.45,2081.01 25153.29,2081.01 25241.97,1992.32 D11_ROW8.1@25456,1992.32
NetD12_ROW1_1: D12_ROW1.1 H12_ROW1.2 | length 742.5
  Top Layer w10: D12_ROW1.1@2809.94,286.01 2810.92,286.01 3155,630.09 H12_ROW1.2@3155,885
NetD12_ROW2_1: D12_ROW2.1 H12_ROW2.2 | length 709.3
  Top Layer w10: D12_ROW2.1@6573.05,286.01 6574.04,286.01 6838,549.97 H12_ROW2.2@6838,885
NetD12_ROW3_1: D12_ROW3.1 H12_ROW3.2 | length 733.7
  Top Layer w10: D12_ROW3.1@9798.58,286.01 9799.56,286.01 9812.28,298.72 9812.28,427.28 10120,735 H12_ROW3.2@10120,886
NetD12_ROW4_1: D12_ROW4.1 H12_ROW4.2 | length 707.8
  Top Layer w10: D12_ROW4.1@13561.69,286.01 13562.67,286.01 13823,546.33 H12_ROW4.2@13823,885
NetD12_ROW5_1: D12_ROW5.1 H12_ROW5.2 | length 721.7
  Top Layer w10: D12_ROW5.1@16787.22,286.01 16788.2,286.01 16800.92,298.72 16800.92,453.71 17082,734.79 H12_ROW5.2@17082,885
NetD12_ROW6_1: D12_ROW6.1 H12_ROW6.2 | length 708.1
  Top Layer w10: D12_ROW6.1@20550.33,286.01 20551.31,286.01 20810,544.69 H12_ROW6.2@20810,886
NetD12_ROW7_1: D12_ROW7.1 H12_ROW7.2 | length 701.1
  Top Layer w10: D12_ROW7.1@23775.85,286.01 23776.84,286.01 24021,530.17 H12_ROW7.2@24021,885
NetD12_ROW8_1: D12_ROW8.1 H12_ROW8.2 | length 1131.4
  Bottom Layer w10: H12_ROW8.2@24232,2362.01 24252,2342.01 24357.56,2342.01 24395,2304.56 24395,2270 24618.75,2046.25 25135.09,2046.25 25189.02,1992.32 D12_ROW8.1@25190,1992.32
NetD13_ROW1_1: D13_ROW1.1 H13_ROW1.2 | length 734
  Top Layer w10: D13_ROW1.1@3347.53,286.01 3348.51,286.01 3672,609.5 H13_ROW1.2@3672,885
NetD13_ROW2_1: D13_ROW2.1 H13_ROW2.2 | length 974.1
  Top Layer w10: H13_ROW2.2@6838,1207 6838,1060.55 6904,994.55 6904,571.44 6841.85,509.28 D13_ROW2.1@6841.85,286.01
NetD13_ROW3_1: D13_ROW3.1 H13_ROW3.2 | length 779
  Top Layer w10: D13_ROW3.1@10336.16,286.01 10348.88,298.72 10359.52,298.72 10707.3,646.51 10707.3,691.6 10659,739.9 H13_ROW3.2@10659,885
NetD13_ROW4_1: D13_ROW4.1 H13_ROW4.2 | length 973.1
  Top Layer w10: H13_ROW4.2@13823,1207 13823,1060.55 13889,994.55 13889,344.52 13844.18,299.71 13844.18,298.72 13831.47,286.01 D13_ROW4.1@13830.48,286.01
NetD13_ROW5_1: D13_ROW5.1 H13_ROW5.2 | length 706.8
  Top Layer w10: D13_ROW5.1@17324.8,286.01 17324.8,506.45 17565,746.65 17565,865 H13_ROW5.2@17585,885
NetD13_ROW6_1: D13_ROW6.1 H13_ROW6.2 | length 973.5
  Top Layer w10: H13_ROW6.2@20810,1208 20810,1061.55 20876,995.55 20876,342.89 20832.82,299.71 20832.82,298.72 20820.11,286.01 D13_ROW6.1@20819.12,286.01
NetD13_ROW7_1: D13_ROW7.1 H13_ROW7.2 | length 715.8
  Top Layer w10: D13_ROW7.1@24313.44,286.01 24314.43,286.01 24594,565.58 H13_ROW7.2@24594,885
NetD13_ROW8_1: D13_ROW8.1 H13_ROW8.2 | length 1386.8
  Bottom Layer w10: H13_ROW8.2@23712,2362.01 23732,2342.01 23837.56,2342.01 24016.34,2163.22 24016.34,2162.11 24186.13,1992.32 D13_ROW8.1@24945,1992.32
PWR+: C1.2 C2.1 C3.2 FB1.2 J1.1 J1.3
  other v2: 2298,2285
ROW1: C4_ROW1.2 D1_ROW1.2 D2_ROW1.2 D3_ROW1.2 D4_ROW1.2 D5_ROW1.2 D6_ROW1.2 D7_ROW1.2 D8_ROW1.2 D9_ROW1.2 D10_ROW1.2 D11_ROW1.2 D12_ROW1.2 D13_ROW1.2 J1.5 R6_ROW1.2 | length 2303.4
  Top Layer w10: D10_ROW1.2@2272.35,161.99 D10_ROW1.2@2275.36,165 ; v2(2398,2285) J1.5@2398,2289.92
  Bottom Layer w10: v1(2360,155) 2360,547.65 2415.3,602.95 2415.3,1440.49 2359.64,1496.15 2359.64,2246.64 v2(2398,2285) 2398,2384.54 C4_ROW1.2@2400,2386.54
  other v1: 2405,155 2450,155
ROW2: C4_ROW2.2 D1_ROW2.2 D2_ROW2.2 D3_ROW2.2 D4_ROW2.2 D5_ROW2.2 D6_ROW2.2 D7_ROW2.2 D8_ROW2.2 D9_ROW2.2 D10_ROW2.2 D11_ROW2.2 D12_ROW2.2 D13_ROW2.2 J1.7 R6_ROW2.2 | length 2767
  Top Layer w10: v2(2498,2285) J1.7@2498,2289.92
  Bottom Layer w10: C4_ROW2.2@2500,2386.54 2498,2384.54 v2(2498,2285) 2459.64,2246.64 2459.64,1800.83 2512,1748.47 2512,1363 3698.79,176.21 3698.79,156.21 v1(3700,155)
  other v1: 3745,155 3790,155
ROW3: C4_ROW3.2 D1_ROW3.2 D2_ROW3.2 D3_ROW3.2 D4_ROW3.2 D5_ROW3.2 D6_ROW3.2 D7_ROW3.2 D8_ROW3.2 D9_ROW3.2 D10_ROW3.2 D11_ROW3.2 D12_ROW3.2 D13_ROW3.2 J1.9 R6_ROW3.2 | length 6188.9
  Top Layer w10: v2(2598,2285) J1.9@2598,2289.92
  Bottom Layer w10: C4_ROW3.2@2600,2386.54 2598,2384.54 v2(2598,2285) 2559.64,2246.64 2559.64,1493.15 3345.4,707.4 3988.79,64 7104,64 7155,115 7219,115 v1(7220,114)
  other v1: 7265,114 7310,114
ROW4: C4_ROW4.2 D1_ROW4.2 D2_ROW4.2 D3_ROW4.2 D4_ROW4.2 D5_ROW4.2 D6_ROW4.2 D7_ROW4.2 D8_ROW4.2 D9_ROW4.2 D10_ROW4.2 D11_ROW4.2 D12_ROW4.2 D13_ROW4.2 J1.11 R6_ROW4.2 | length 9475.4
  Top Layer w10: v2(2698,2285) J1.11@2698,2289.92
  Bottom Layer w10: C4_ROW4.2@2700,2386.54 2698,2384.54 v2(2698,2285) 2659.64,2246.64 2659.64,1644.2 4223.83,80 6894.64,80 6954.64,140 8799.62,140 8819.62,120 v1(10690,120)
  other v1: 10735,120 10780,120
ROW5: C4_ROW5.2 D1_ROW5.2 D2_ROW5.2 D3_ROW5.2 D4_ROW5.2 D5_ROW5.2 D6_ROW5.2 D7_ROW5.2 D8_ROW5.2 D9_ROW5.2 D10_ROW5.2 D11_ROW5.2 D12_ROW5.2 D13_ROW5.2 J1.13 R6_ROW5.2 | length 12912.4
  Top Layer w10: v2(2798,2285) J1.13@2798,2289.92
  Bottom Layer w10: C4_ROW5.2@2800,2386.54 2798,2384.54 v2(2798,2285) 2759.64,2246.64 2759.64,1566.82 4230.46,96 6888.02,96 6952.02,160 10776.77,160 10800.77,136 v1(14185,136)
  other v1: 14230,136 14275,136
ROW6: C4_ROW6.2 D1_ROW6.2 D2_ROW6.2 D3_ROW6.2 D4_ROW6.2 D5_ROW6.2 D6_ROW6.2 D7_ROW6.2 D8_ROW6.2 D9_ROW6.2 D10_ROW6.2 D11_ROW6.2 D12_ROW6.2 D13_ROW6.2 J1.15 R6_ROW6.2 | length 16346.1
  Top Layer w10: v2(2898,2285) J1.15@2898,2289.92
  Bottom Layer w10: C4_ROW6.2@2900,2386.54 2898,2384.54 v2(2898,2285) 2859.64,2246.64 2859.64,2169.11 2860,2168.75 2860,1489.09 4237.09,112 6881.39,112 6945.39,176 14271.77,176 14295.77,152 v1(17680,152)
  other v1: 17725,152 17770,152
ROW7: C4_ROW7.2 D1_ROW7.2 D2_ROW7.2 D3_ROW7.2 D4_ROW7.2 D5_ROW7.2 D6_ROW7.2 D7_ROW7.2 D8_ROW7.2 D9_ROW7.2 D10_ROW7.2 D11_ROW7.2 D12_ROW7.2 D13_ROW7.2 J1.17 R6_ROW7.2 | length 19812.7
  Top Layer w10: v2(2998,2285) J1.17@2998,2289.92
  Bottom Layer w10: C4_ROW7.2@3000,2386.54 2998,2384.54 v2(2998,2285) 2935,2222 2935,2202.25 2936.36,2200.89 2936.36,2169.11 2935,2167.75 2935,1478.23 3260.73,1152.5 3279.27,1152.5 3605,826.77 3605,775 4252,128 6874.76,128 6938.76,192 17769.77,192 17806.77,155 v1(21175,155)
  other v1: 21220,155 21265,155
ROW8: C4_ROW8.2 D1_ROW8.2 D2_ROW8.2 D3_ROW8.2 D4_ROW8.2 D5_ROW8.2 D6_ROW8.2 D7_ROW8.2 D8_ROW8.2 D9_ROW8.2 D10_ROW8.2 D11_ROW8.2 D12_ROW8.2 D13_ROW8.2 J1.19 R6_ROW8.2 | length 31134.6
  Top Layer w10: v2(3098,2285) J1.19@3098,2289.92
  Bottom Layer w10: C4_ROW8.2@3100,2386.54 3098,2384.54 v2(3098,2285) 3036.36,2223.36 3036.36,1837.48 3034,1835.12 3034,1436 3674,796 4009.21,796 4358.21,447 4877.71,447 5100.6,224.12 25290.91,224.12 25862.79,796 25910.77,796 25926,780.77 25926,748.37 25369.74,192.12 24683.82,192.12 24673.83,182.12 24673.83,158.83 v1(24670,155) ; v1(24760,155) 24761.84,153.16 24761.84,134.41 24791.26,105 26309.14,105 26315,110.86 26540,335.86 26540,1720 26391.69,1868.31 D8_ROW8.2@26301.68,1868.31 D9_ROW8.2@26039,1868.31 D10_ROW8.2@25748,1868.31 D11_ROW8.2@25456,1868.31 D12_ROW8.2@25190,1868.31 D13_ROW8.2@24945,1868.31 24944.02,1868.31 D13_ROW8.2@24931.3,1855.59
  other v1: 24715,155
pads on no net: R5.MP1 R5.MP2

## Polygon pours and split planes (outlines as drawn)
GND on Top Layer "GND_L01_P024" (solid, pour order 24): 3467.87,2236.62 3496.75,2265.49 3496.75,2508.65 3439.65,2565.75 530.75,2565.75 520,2555 520,1990 620,1990 620,2265 830,2475 3130,2475 3230,2375 3230,2236.62
ROW8 on Top Layer "ROW8_L01_P011" (solid, pour order 11): 26250,194 26250,115 24615.24,115 24615.24,42 24550.24,42 24550.24,191 24547.24,194
ROW7 on Top Layer "ROW7_L01_P009" (solid, pour order 9): 24371.92,194 24371.92,115 21120.92,115 21120.92,42 21055.92,42 21055.92,191 21052.92,194
ROW6 on Top Layer "ROW6_L01_P008" (solid, pour order 8): 20877.6,194 20877.6,115 17626.6,115 17626.6,42 17561.6,42 17561.6,191 17558.6,194
ROW5 on Top Layer "ROW5_L01_P007" (solid, pour order 7): 17383.28,194 17383.28,115 14132.28,115 14132.28,42 14067.28,42 14067.28,191 14064.28,194
ROW4 on Top Layer "ROW4_L01_P006" (solid, pour order 6): 13888.96,194 13888.96,102 10637.96,102 10637.96,42 10572.96,42 10572.96,191 10569.96,194
ROW3 on Top Layer "ROW3_L01_P004" (solid, pour order 4): 10394.64,194 10394.64,95 7143.64,95 7143.64,42 7078.64,42 7078.64,191 7075.64,194
ROW2 on Top Layer "ROW2_L01_P002" (solid, pour order 2): 6900.32,194 6900.32,115 3649.32,115 3649.32,42 3584.32,42 3584.32,191 3581.32,194
ROW1 on Top Layer "ROW1_L01_P000" (solid, pour order 0): 3406,194 3406,115 155,115 155,42 90,42 90,191 87,194
GND on Bottom Layer "GND_L02_P023" (solid, pour order 23): 0,0 0,2625 26720,2625 26720,0
GND on Bottom Layer "GND_L02_P020" (solid, pour order 20): 3360,2240 3360,2488 3288,2560 1900,2560 1745,2405 1745,2330 2135,2330 2135,2430 3140,2430 3140,2240
PWR+ on Bottom Layer "PWR+_L02_P018" (solid, pour order 18): 1805,2328.35 1806.65,2330 2340,2330 2340,2235 1805,2235
ROW7 on Bottom Layer "ROW7_L02_P016" (solid, pour order 16): 21155,195 21290,195 21290,115 21155,115
ROW6 on Bottom Layer "ROW6_L02_P015" (solid, pour order 15): 17660,195 17795,195 17795,115 17660,115
ROW5 on Bottom Layer "ROW5_L02_P014" (solid, pour order 14): 14165,195 14300,195 14300,115 14165,115
ROW4 on Bottom Layer "ROW4_L02_P013" (solid, pour order 13): 10670,195 10805,195 10805,115 10670,115
ROW3 on Bottom Layer "ROW3_L02_P012" (solid, pour order 12): 7197.59,175 7332.59,175 7332.59,95 7197.59,95
ROW8 on Bottom Layer "ROW8_L02_P017" (solid, pour order 17): 24650,195 24785,195 24785,115 24650,115
ROW2 on Bottom Layer "ROW2_L02_P003" (solid, pour order 3): 3680,195 3815,195 3815,115 3680,115
ROW1 on Bottom Layer "ROW1_L02_P001" (solid, pour order 1): 2340,195 2475,195 2475,115 2340,115

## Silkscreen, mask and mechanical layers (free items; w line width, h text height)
Bottom Overlay:
  lines w10: 2330,2455 2330,2450 ; 2330,2475 2330,2450 ; 2360,2420 2330,2450 ; 2445,2545 2445,2440 2460,2425 ; 2550,2470 2550,2430 2560,2420 ; 2740,2420 2750,2430 2750,2545 ; 2780,2485 2775,2490 2775,2530 2795,2550 ; 2850,2480 2850,2430 2860,2420 ; 3040,2425 3050,2435 3050,2465 3085,2500 3085,2535 3097.5,2547.5 ; 3140,2420 3160,2440 3160,2480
